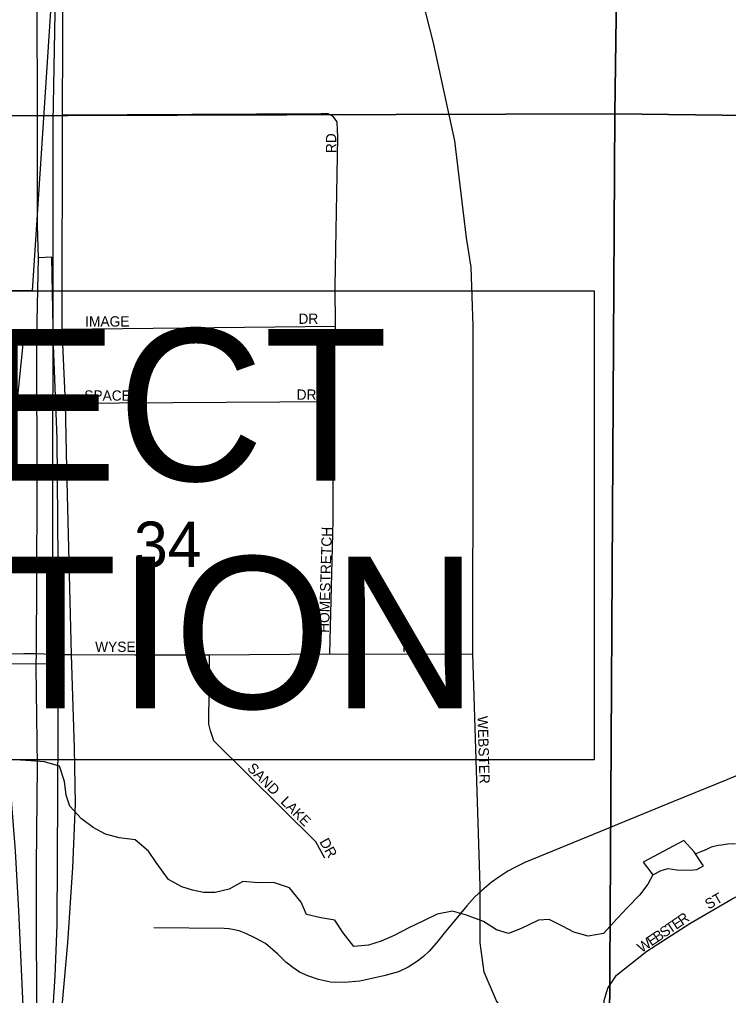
# Model space of a CAD drawing. Extents: x 8.5 to 81.5, y -1.2 to 22.4.
# Drawn here: x 52.663 to 53.317, y 15.95 to 16.85 of the extents above; entities that cross this region are included whole.
import ezdxf

# ---------------------------------------------------------------- set-up
doc = ezdxf.new("R2010")
doc.units = 0
for name, color, linetype in [('GM_X_City_Street', 7, 'Continuous'), ('GM_X_City_Street_Text', 7, 'Continuous'), ('GM_X_Corporation', 7, 'Continuous'), ('GM_X_Interchange_Ramps', 7, 'Continuous'), ('GM_X_Interstate_Route', 7, 'Continuous'), ('GM_X_Minor_Lake', 7, 'Continuous'), ('GM_X_Minor_River', 7, 'Continuous'), ('GM_X_Rail_Line', 7, 'Continuous'), ('GM_X_Section', 7, 'Continuous'), ('GM_X_Section_Text', 7, 'Continuous'), ('GM_X_Township_Road', 7, 'Continuous'), ('SH_Text', 7, 'Continuous')]:
    doc.layers.add(name, color=color, linetype=linetype)

msp = doc.modelspace()

# ---------------------------------------------------------------- linework, layer by layer
at = {"layer": 'GM_X_City_Street'}
for points in [[(53.20224, 15.85881), (53.12702, 15.91231), (53.10327, 15.94556), (53.09179, 15.97208), (53.08823, 15.99901), (53.08823, 16.05127), (53.08151, 16.26523), (53.0819, 16.461), (53.0819, 16.56789), (53.07993, 16.62212), (53.07557, 16.64904), (53.06488, 16.73851), (53.04509, 16.82877), (53.03473, 16.86998), (53.0257, 16.91508), (53.02055, 16.96852), (53.01818, 17.02355), (53.01748, 17.18118)], [(52.69603, 15.77377), (52.6955, 15.83392), (52.69812, 15.88662), (52.70272, 15.94055), (52.70799, 15.99908), (52.71259, 16.06845), (52.71491, 16.12731), (52.71424, 16.1786), (52.71127, 16.26476), (52.707, 16.43672), (52.70569, 16.49656), (52.70281, 16.56497), (52.70277, 16.57092), (52.70305, 16.76211), (52.70361, 16.89908)], [(52.9495, 16.26545), (52.95274, 16.38846), (52.953, 16.49809), (52.95474, 16.56772), (52.95463, 16.60415), (52.95689, 16.74186), (52.95619, 16.75614), (52.95229, 16.76121), (52.948, 16.76341), (52.94151, 16.76354), (52.70305, 16.76211)], [(52.70281, 16.56497), (52.95474, 16.56772)], [(52.70569, 16.49656), (52.953, 16.49809)], [(52.66736, 16.26574), (52.67904, 16.26592), (52.69911, 16.26476), (52.71127, 16.26476)], [(52.71127, 16.26476), (52.76973, 16.26471)], [(52.76973, 16.26471), (52.83857, 16.26466), (52.9495, 16.26545), (53.08151, 16.26523)], [(52.94508, 16.07709), (52.93677, 16.09216), (52.84272, 16.18517), (52.8396, 16.19452), (52.83804, 16.20076), (52.83857, 16.26466)], [(53.20224, 15.85881), (53.20255, 15.94581), (53.20611, 15.9572), (53.21393, 15.96928), (53.24201, 15.99125), (53.28154, 16.01695), (53.32067, 16.03971), (53.34557, 16.05181), (53.36692, 16.06034), (53.384, 16.06177)]]:
    msp.add_lwpolyline(points, dxfattribs=at)
at = {"layer": 'GM_X_Corporation'}
msp.add_lwpolyline([(52.69765, 16.9574), (52.69424, 16.75582), (52.69373, 16.25605), (51.65683, 16.25633)], dxfattribs=at)
at = {"layer": 'GM_X_Interchange_Ramps'}
for points in [[(52.69911, 16.26476), (52.69976, 16.27725), (52.69798, 16.46399), (52.69459, 16.55013), (52.69304, 16.63135), (52.6808, 16.63072), (52.68022, 16.63069)], [(52.67923, 16.55704), (52.66707, 16.55704), (52.65078, 16.39628), (52.64551, 16.34137), (52.64617, 16.27528), (52.64617, 16.26541)], [(52.64617, 16.26541), (52.64617, 16.25292), (52.65951, 16.08355), (52.66246, 16.02897), (52.66872, 15.89317), (52.67923, 15.89383)], [(52.67891, 15.8718), (52.69008, 15.8718), (52.69634, 15.96814), (52.69812, 16.01552), (52.69944, 16.25522), (52.69911, 16.26476)]]:
    msp.add_lwpolyline(points, dxfattribs=at)
at = {"layer": 'GM_X_Interstate_Route'}
for points in [[(52.67994, 16.66087), (52.67985, 16.66395), (52.68012, 16.76751), (52.67962, 16.86199)], [(52.67882, 16.25558), (52.67904, 16.26592), (52.67932, 16.33684), (52.67958, 16.4137), (52.67923, 16.55704), (52.6808, 16.63072), (52.67994, 16.66087)], [(52.67926, 15.76341), (52.67904, 15.7735), (52.67891, 15.8718), (52.67923, 15.89383), (52.67904, 16.0704), (52.67985, 16.16236), (52.67878, 16.25324), (52.67882, 16.25558)]]:
    msp.add_lwpolyline(points, dxfattribs=at)
at = {"layer": 'GM_X_Minor_Lake'}
for points in [[(53.23868, 16.07333), (53.24757, 16.06175), (53.25525, 16.06577), (53.26174, 16.06754), (53.2697, 16.06623), (53.28185, 16.06598), (53.28794, 16.06662), (53.29408, 16.06991), (53.29261, 16.07222), (53.2856, 16.08301), (53.27593, 16.09346)], [(53.27593, 16.09346), (53.23868, 16.07333)]]:
    msp.add_lwpolyline(points, dxfattribs=at)
at = {"layer": 'GM_X_Minor_River'}
for points in [[(53.24757, 16.06175), (53.24285, 16.0531), (53.23505, 16.043), (53.22419, 16.03145), (53.21449, 16.02138), (53.20206, 16.00758), (53.18796, 16.00521), (53.17474, 16.0089), (53.16421, 16.01444), (53.15179, 16.02039), (53.1419, 16.01984), (53.12541, 16.01181), (53.11431, 16.00748), (53.10336, 16.01113), (53.09135, 16.0186), (53.07552, 16.02462), (53.06267, 16.02831), (53.04856, 16.02556), (53.03591, 16.01936), (53.02248, 16.01279), (53.00905, 16.00585), (52.99678, 16.0004), (52.98532, 15.99684), (52.97162, 15.9956), (52.96199, 16.00834), (52.95424, 16.0199), (52.94137, 16.02206), (52.92813, 16.025), (52.92304, 16.0365), (52.91228, 16.04965), (52.89756, 16.05451), (52.88388, 16.05442), (52.86947, 16.05547), (52.8568, 16.04851), (52.84382, 16.04536), (52.83319, 16.04558), (52.82297, 16.04769), (52.81315, 16.05056), (52.80075, 16.05728), (52.78928, 16.07309), (52.78227, 16.0835), (52.76994, 16.09401), (52.75516, 16.09584), (52.74269, 16.09914), (52.73142, 16.10545), (52.72056, 16.11328), (52.70977, 16.1249), (52.70655, 16.13523), (52.7049, 16.14781), (52.70024, 16.16196), (52.68627, 16.16605), (52.67374, 16.16669), (52.65971, 16.16774)], [(53.32362, 16.09034), (53.31641, 16.0901), (53.31069, 16.08908), (53.30765, 16.08876), (53.30117, 16.08737), (53.29695, 16.08517), (53.2916, 16.083), (53.28705, 16.08106)]]:
    msp.add_lwpolyline(points, dxfattribs=at)
at = {"layer": 'GM_X_Rail_Line'}
msp.add_lwpolyline([(53.33182, 16.15599), (53.31575, 16.14943), (53.26667, 16.12925), (53.18731, 16.09672), (53.12951, 16.07321), (53.12011, 16.06861), (53.11374, 16.06508), (53.10531, 16.05969), (53.09826, 16.0547), (53.08984, 16.04735), (53.08337, 16.04157), (53.07583, 16.03304), (53.06417, 16.01903), (53.05623, 16.00953), (53.048, 15.99905), (53.04124, 15.99141), (53.03586, 15.98641), (53.03037, 15.9821), (53.02185, 15.97671), (53.01293, 15.9724), (52.99931, 15.96868), (52.97724, 15.96373), (52.96277, 15.96251), (52.9502, 15.96285), (52.93926, 15.96515), (52.92927, 15.96848), (52.92172, 15.97211), (52.91535, 15.97622), (52.90889, 15.98122), (52.90164, 15.98847), (52.89027, 15.99846), (52.88048, 16.00369), (52.87213, 16.00775), (52.86592, 16.00997), (52.85661, 16.01197), (52.85203, 16.01226), (52.78727, 16.01278)], dxfattribs=at)
at = {"layer": 'GM_X_Section'}
for points in [[(52.21491, 17.8371), (53.22721, 17.83517), (53.21242, 16.76328), (52.20343, 16.76022)], [(53.22721, 17.83517), (53.85767, 17.82864), (53.58921, 17.24628), (53.49556, 16.87689), (53.50964, 16.7596), (53.21242, 16.76328)], [(52.20343, 16.76022), (53.21242, 16.76328), (53.20654, 15.7628), (52.20331, 15.76418)], [(53.21242, 16.76328), (53.50964, 16.7596), (53.51356, 16.42322), (53.4626, 16.00759), (53.38319, 15.83221), (53.38111, 15.76219), (53.20654, 15.7628)]]:
    msp.add_lwpolyline(points, close=True, dxfattribs=at)
at = {"layer": 'GM_X_Township_Road'}
msp.add_lwpolyline([(52.55496, 16.26495), (52.64617, 16.26541), (52.66736, 16.26574)], dxfattribs=at)
at = {"layer": 'SH_Text'}
for points in [[(52.75122, 17.76347), (52.6752, 16.60026), (52.09044, 16.60026)], [(52.09044, 16.60026), (53.19324, 16.60026), (53.19324, 16.16765), (52.09044, 16.16765)]]:
    msp.add_lwpolyline(points, close=True, dxfattribs=at)

# ---------------------------------------------------------------- texts
at = {"layer": 'GM_X_City_Street_Text'}
for s, height, rotation, p in [('RD', 0.00947, 90, (52.9555, 16.72717)), ('IMAGE', 0.00947, 0.00001, (52.72395, 16.56729)), ('DR', 0.00947, 0.00001, (52.92062, 16.56978)), ('SPACE', 0.00947, 0.00001, (52.72312, 16.49895)), ('DR', 0.00947, 0.00001, (52.91895, 16.49978)), ('HOMESTRETCH', 0.0094697, 88.33046, (52.94884, 16.28472)), ('WYSE', 0.00947, 0.00001, (52.73312, 16.26729)), ('RD', 0.00947, 0.00001, (53.01645, 16.26728)), ('WEBSTER', 0.00947, 271.76147, (53.08573, 16.20806)), ('SAND', 0.00947, 315.00405, (52.87271, 16.15926)), ('LAKE', 0.00947, 315, (52.90354, 16.12843)), ('DR', 0.00947, 299.35646, (52.93967, 16.09221)), ('ST', 0.00947, 29.73647, (53.2989, 16.02955)), ('T', 0.00947, 34.01595, (53.26338, 16.0072)), ('E', 0.00947, 34.01595, (53.2689, 16.01093)), ('R', 0.00947, 35.54062, (53.27465, 16.01482)), ('B', 0.00947, 34.01331, (53.25163, 15.99927)), ('S', 0.00947, 34.01595, (53.25785, 16.00347)), ('W', 0.00947, 34.00715, (53.23712, 15.98948)), ('E', 0.00947, 34.02851, (53.24611, 15.99554))]:
    msp.add_text(s, height=height, rotation=rotation, dxfattribs=at).set_placement(p)
at = {"layer": 'GM_X_Section_Text'}
msp.add_text('34', height=0.041856, rotation=0.00001, dxfattribs=at).set_placement((52.76895, 16.34556))
at = {"layer": 'SH_Text'}
for s, p in [('PROJECT', (52.12942, 16.42509)), ('LOCATION', (52.12942, 16.21509))]:
    msp.add_text(s, height=0.14, dxfattribs=at).set_placement(p)

doc.saveas('drawing.dxf')
